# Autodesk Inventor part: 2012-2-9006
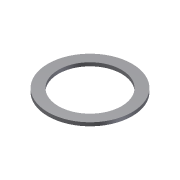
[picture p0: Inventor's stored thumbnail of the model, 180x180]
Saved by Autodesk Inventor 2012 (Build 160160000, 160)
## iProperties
Created: 2011-12
Part Number: 2012-2-9006
Material: Default
Document SubType Name: Modeling
Designer: Admin
Density: 1 g/cm^3
Description: Wear Plate
Author: Admin
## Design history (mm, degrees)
sketch "Sketch1"
  geometry: C1 r 9 at (0, 0); C2 r 12 at (0, 0); 1 further point
  constraints: 2 centre point, 2 coincident
  dimensions: "ShoulderOD" = 18 diameter of C1; "d1" = 3 radial gap between concentric circles of C2 C1
extrude "Extrusion1" new body sketch "Sketch1" distance "d2" = 1; taper "d3" = 0 deg
body "Solid1"
